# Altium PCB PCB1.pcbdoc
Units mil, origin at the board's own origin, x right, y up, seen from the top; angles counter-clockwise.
Board outline 3855 x 2840 mil, 4 copper layers (Top Layer, Inner1, Inner2, Bottom Layer); 26 components, 17 nets, 63 pads, 16 vias.
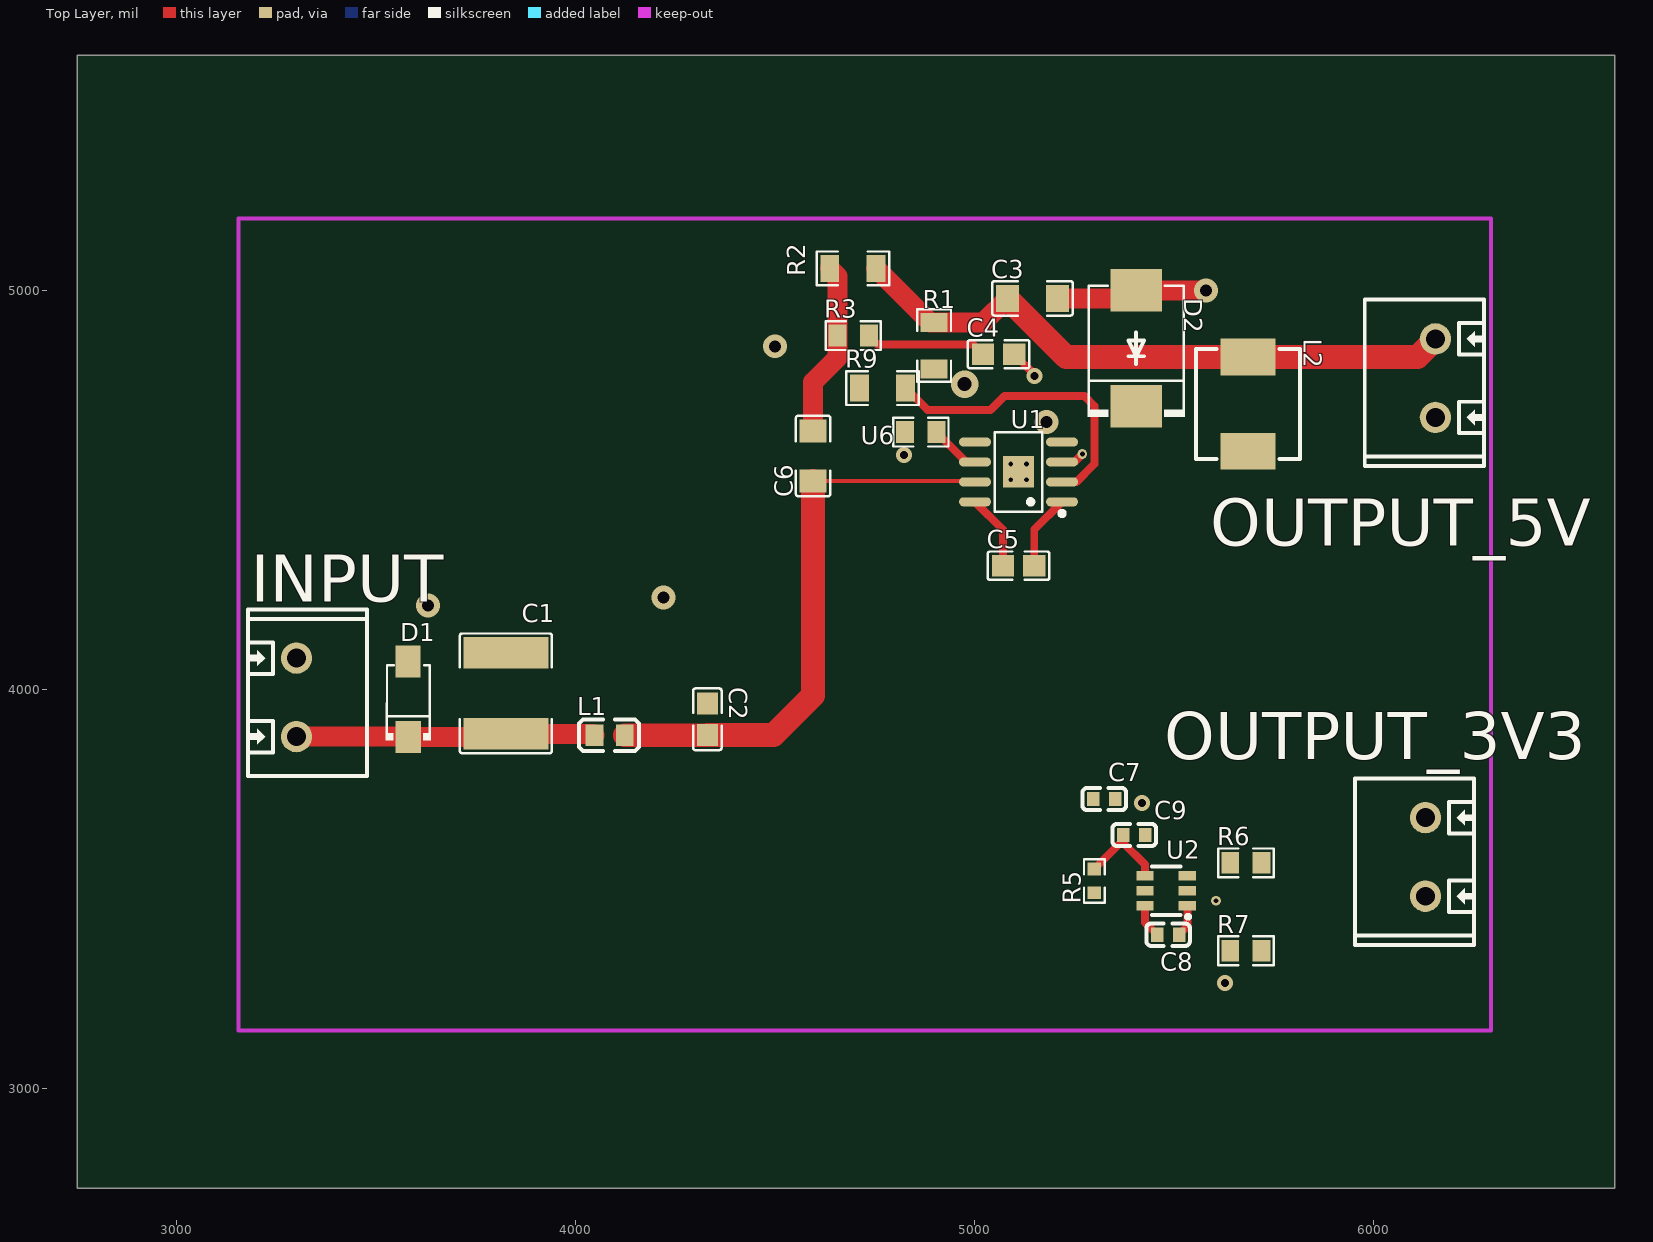
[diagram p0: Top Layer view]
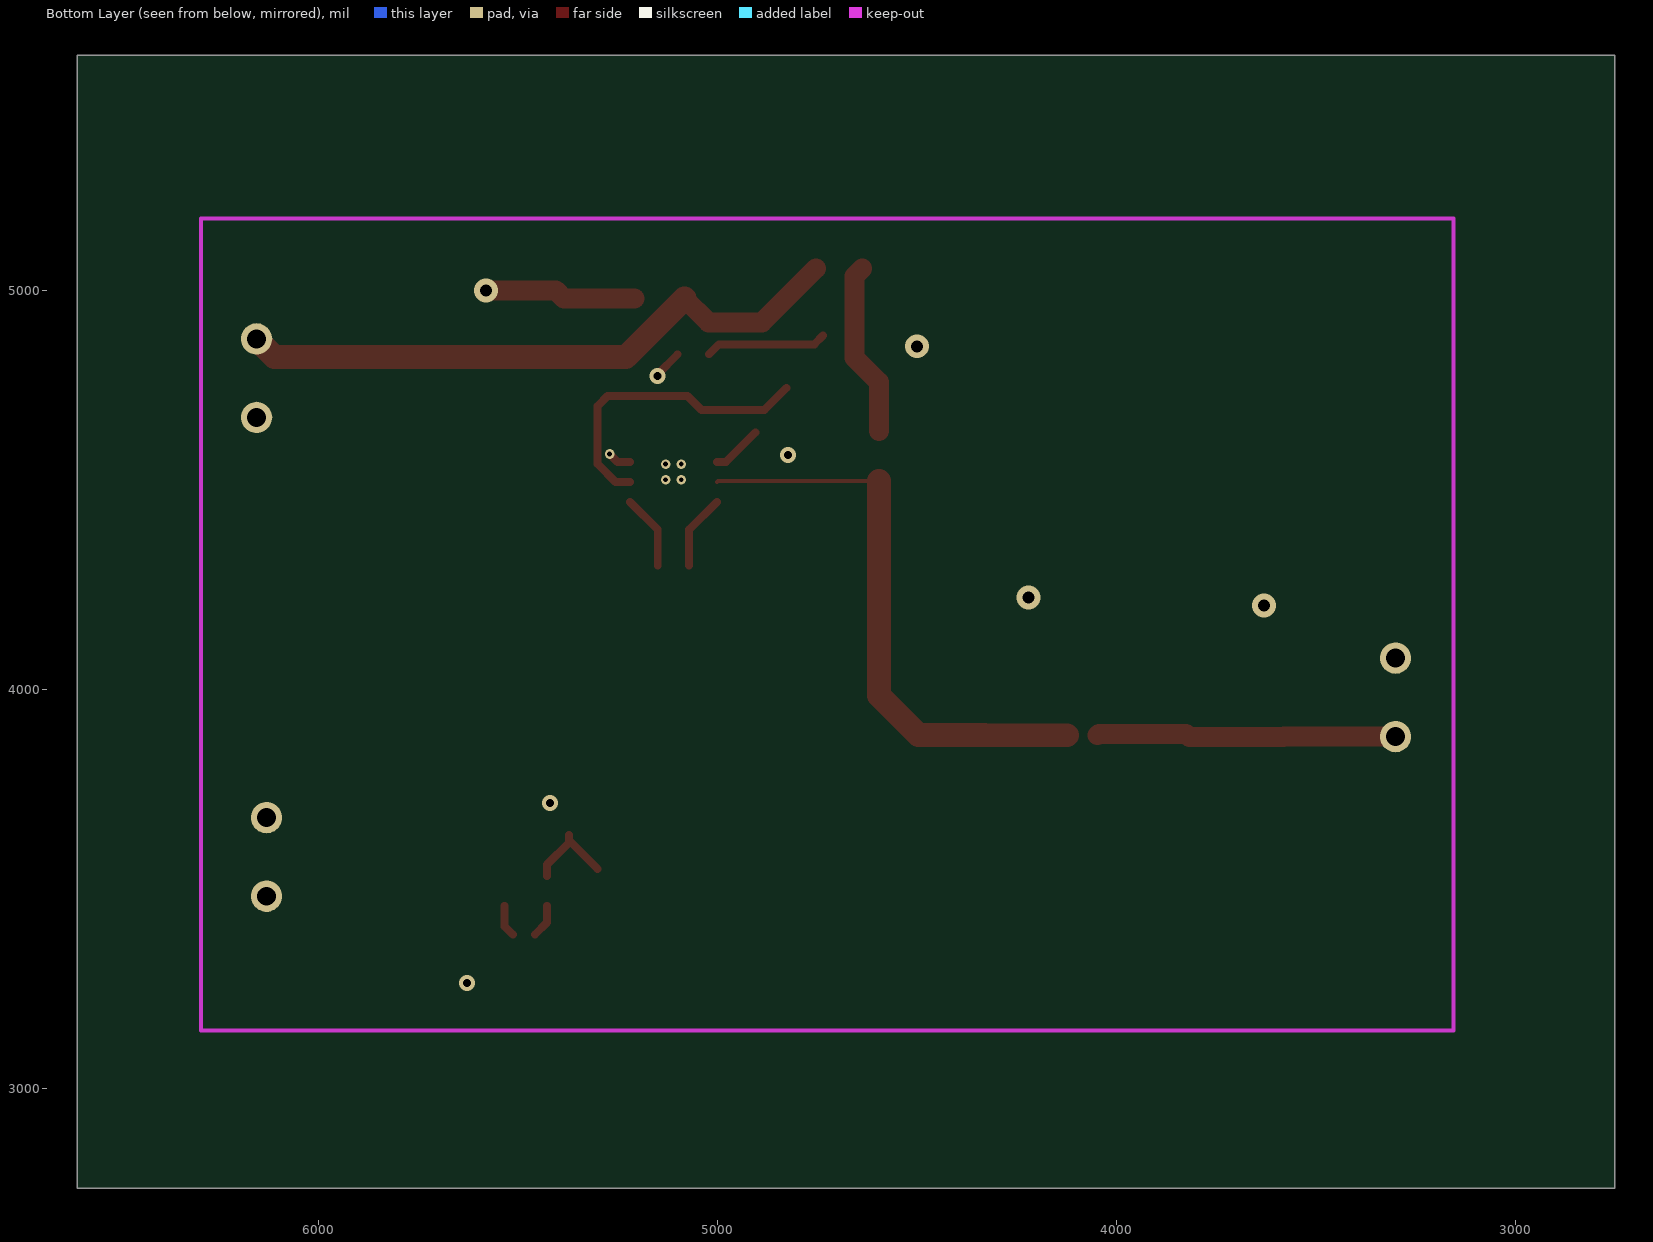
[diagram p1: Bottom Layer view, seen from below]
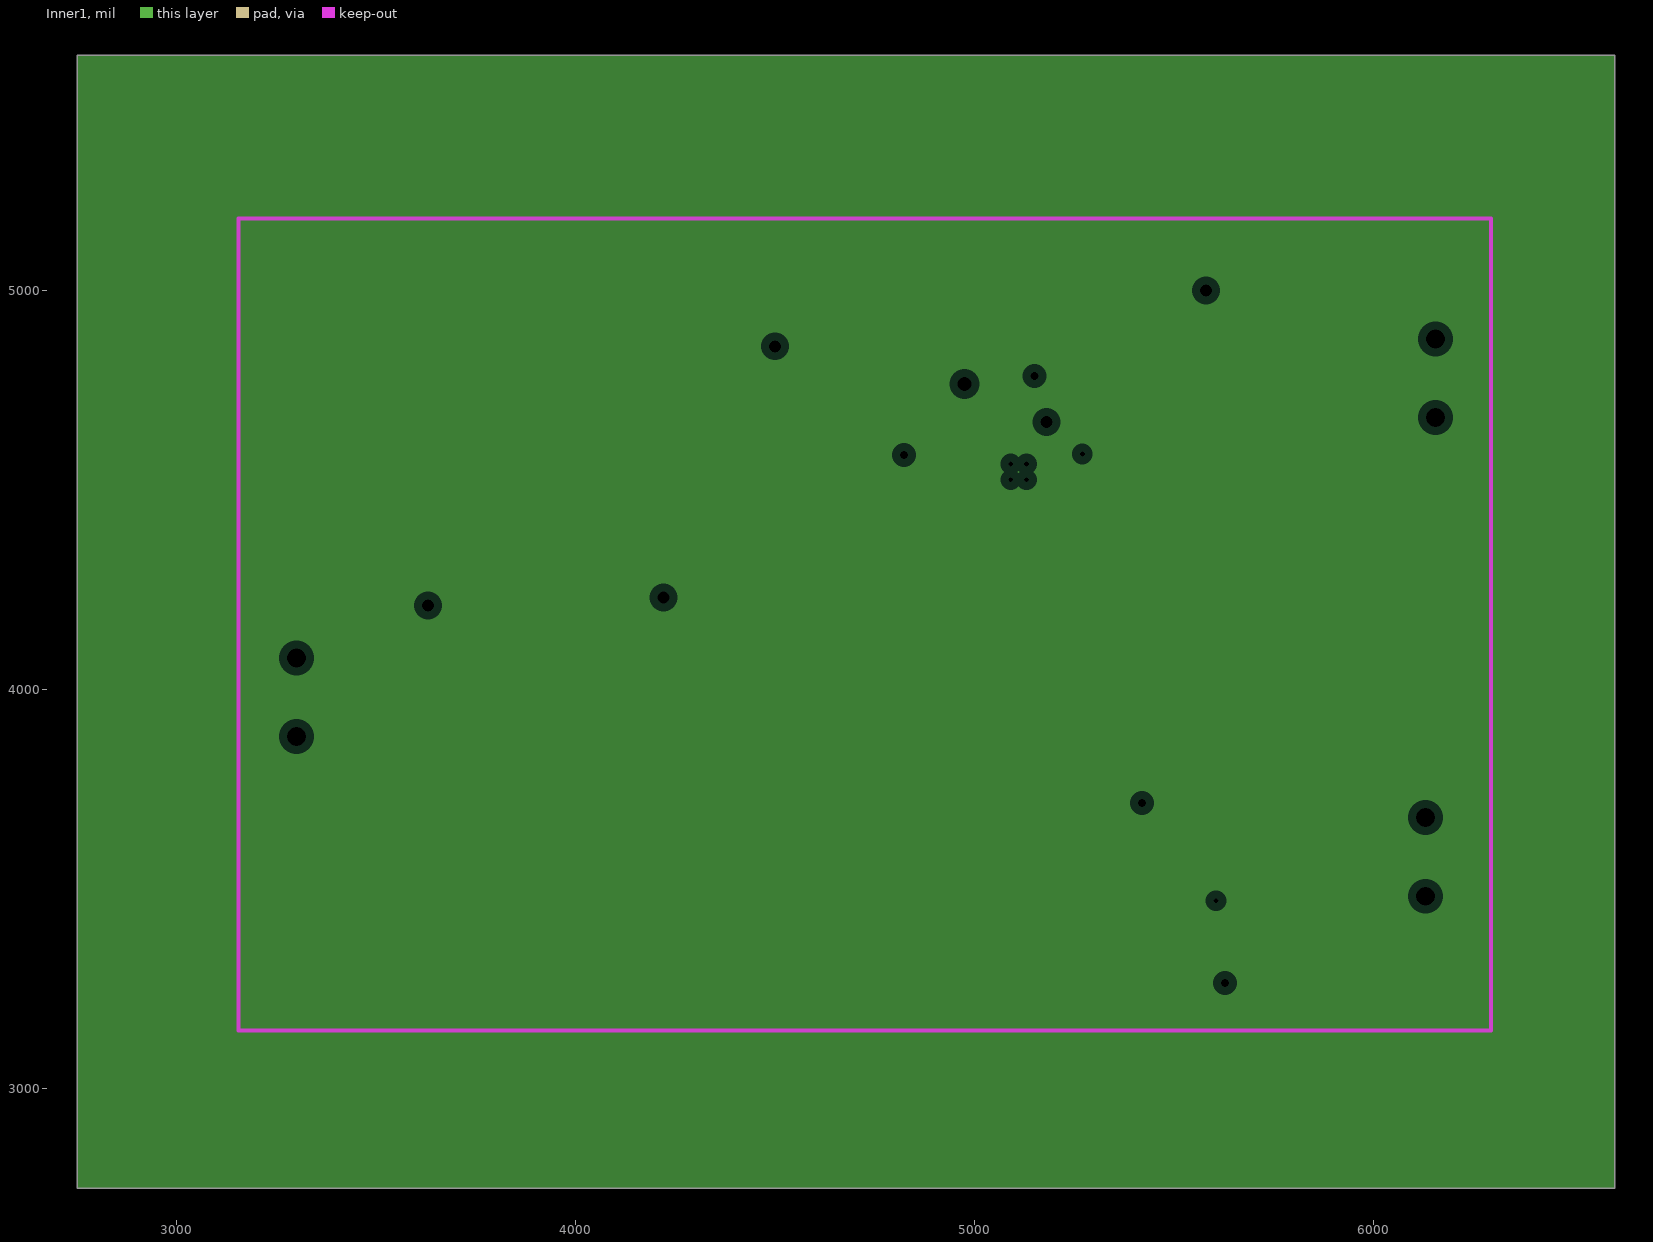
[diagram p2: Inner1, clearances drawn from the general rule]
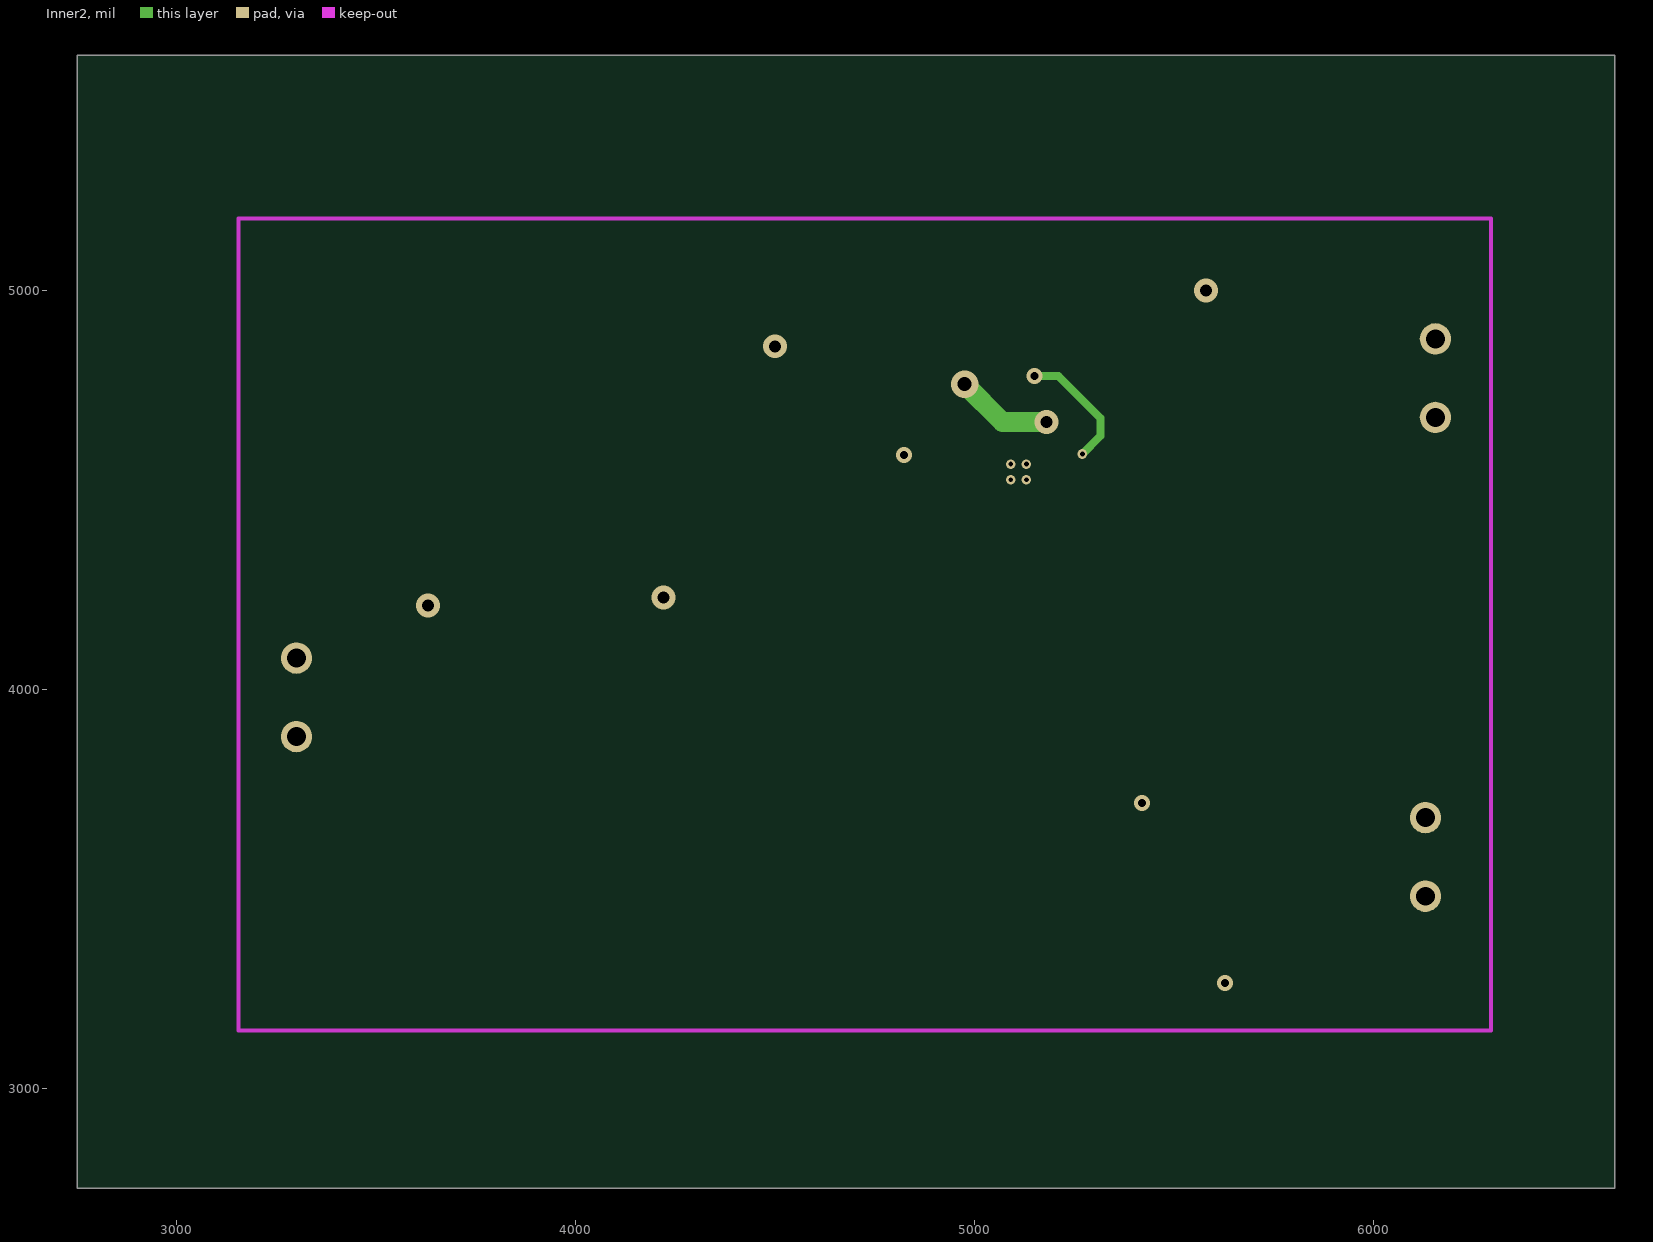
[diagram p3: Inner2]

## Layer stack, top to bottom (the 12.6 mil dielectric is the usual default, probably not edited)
Top Layer: signal copper (thickness not stored)
Dielectric: dielectric 12.6, FR-4, Dk 4.8
Inner1: plane copper (thickness not stored)
Dielectric: dielectric 12.6, FR-4, Dk 4.8
Inner2: signal copper (thickness not stored)
Dielectric: dielectric 12.6, FR-4, Dk 4.8
Bottom Layer: signal copper (thickness not stored)

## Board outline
6605,2750 2750,2750 2750,5590 6605,5590

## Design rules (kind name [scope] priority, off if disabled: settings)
BoardOutlineClearance copperThickness1oz [All] p0: genericclearance=10 ignorepadtopadclearanceinfootprint=FALSE except(0: Arc-SplitContinuation Track-SplitContinuation SMDPad-SplitContinuation THPad-SplitContinuation Via-SplitContinuation Fill-SplitContinuation Poly-SplitContinuation Region-SplitContinuation Text-SplitContinuation; 6: Track-CutoutEdge SMDPad-CutoutEdge THPad-CutoutEdge Via-CutoutEdge Region-CutoutEdge; 11.8: Track-OutlineEdge SMDPad-OutlineEdge THPad-OutlineEdge Via-OutlineEdge Fill-OutlineEdge Region-OutlineEdge Poly-OutlineEdge Text-OutlineEdge Fill-CutoutEdge)
BoardOutlineClearance copperThickness2oz [All] p0: genericclearance=10 ignorepadtopadclearanceinfootprint=FALSE except(0: Arc-SplitContinuation Track-SplitContinuation SMDPad-SplitContinuation THPad-SplitContinuation Via-SplitContinuation Fill-SplitContinuation Poly-SplitContinuation Region-SplitContinuation Text-SplitContinuation; 6: Track-CutoutEdge SMDPad-CutoutEdge THPad-CutoutEdge Via-CutoutEdge Region-CutoutEdge; 11.8: Track-OutlineEdge SMDPad-OutlineEdge THPad-OutlineEdge Via-OutlineEdge Fill-OutlineEdge Region-OutlineEdge Poly-OutlineEdge Text-OutlineEdge Fill-CutoutEdge)
Clearance copperThickness1oz [(InNet('$1N4446') OR InNet('AGND') OR InNet('VIN') OR InNet('GND') OR InNet('$1N1324') OR InNet('$1N1769') OR InNet('$1N1774') OR InNet('$1N1127') OR InNet('$1N1858') OR InNet('$1N3009') OR InNet('$1N3020') OR InNet('$1N3287') OR InNet('$1N1436') OR InNet('$1N3600') OR InNet('$1N3416') OR InNet('$1N4826') OR InNet('$1N1958'))] p1: gap=7 ignorepadtopadclearanceinfootprint=FALSE except(4: Track-Track; 6: Track-SMDPad SMDPad-SMDPad Track-THPad SMDPad-THPad THPad-THPad Track-Via SMDPad-Via THPad-Via Via-Via SMDPad-Fill THPad-Fill Via-Fill Fill-Fill Track-Region SMDPad-Region THPad-Region Via-Region Region-Region Track-Poly SMDPad-Poly THPad-Poly Via-Poly Fill-Poly Region-Poly Poly-Poly Track-Text SMDPad-Text THPad-Text Via-Text Fill-Text Region-Text Poly-Text Text-Text; 6.9: Track-Hole SMDPad-Hole THPad-Hole Via-Hole Fill-Hole Region-Hole Poly-Hole Text-Hole Sheet-Hole; 11.8: Track-Fill Fill-Region Track-Sheet SMDPad-Sheet THPad-Sheet Via-Sheet Fill-Sheet Region-Sheet Poly-Sheet Text-Sheet)
Clearance copperThickness2oz [All] p1: gap=7 ignorepadtopadclearanceinfootprint=FALSE except(6: Track-SMDPad SMDPad-SMDPad Track-THPad SMDPad-THPad THPad-THPad Track-Via SMDPad-Via THPad-Via Via-Via SMDPad-Fill THPad-Fill Via-Fill Fill-Fill Track-Region SMDPad-Region THPad-Region Via-Region Region-Region Track-Poly SMDPad-Poly THPad-Poly Via-Poly Fill-Poly Region-Poly Poly-Poly Track-Text SMDPad-Text THPad-Text Via-Text Fill-Text Region-Text Poly-Text Text-Text; 6.9: Track-Hole SMDPad-Hole THPad-Hole Via-Hole Fill-Hole Region-Hole Poly-Hole Text-Hole Sheet-Hole; 8: Track-Track; 11.8: Track-Fill Fill-Region Track-Sheet SMDPad-Sheet THPad-Sheet Via-Sheet Fill-Sheet Region-Sheet Poly-Sheet Text-Sheet)
DiffPairsRouting differentialPair [All] p1: maxuncoupledlength=10 minlimit=6 maxlimit=6 mostfreqgap=6 toplayer_minwidth=5 toplayer_prefwidth=10 toplayer_maxwidth=100 bottomlayer_minwidth=5 bottomlayer_prefwidth=10 bottomlayer_maxwidth=100 midlayer2_minwidth=5 midlayer2_prefwidth=10 midlayer2_maxwidth=100
PasteMaskExpansion pasteMaskExpansion [All] p1: expansion=0
PlaneConnect innerPlane [All] p1: planeconnectstyle=Relief reliefexpansion=20 reliefentries=4 reliefconductorwidth=10 reliefairgap=10
PolygonConnect copperRegion [All] p1: connectstyle=Relief reliefentries=4 reliefconductorwidth=30 polygonreliefangle="90 Angle" airgapwidth=10
PolygonConnect copperRegion1 [All] p1: connectstyle=Direct reliefentries=4 reliefconductorwidth=10 polygonreliefangle="90 Angle" airgapwidth=10
RoutingVias viaSize [All] p1: viastyle="Through Hole" holewidth=12 minholewidth=11.8 maxholewidth=248 width=24 minwidth=19.7 maxwidth=393.7
SolderMaskExpansion solderMaskExpansion [All] p1: useseparateexpansions=TRUE expansion=2 expansionbottom=2
Width copperThickness1oz [All] p1: maxlimit=100 minlimit=5 preferedwidth=10
Width copperThickness2oz [All] p1: maxlimit=100 minlimit=8 preferedwidth=50

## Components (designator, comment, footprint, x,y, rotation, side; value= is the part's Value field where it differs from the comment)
C1 "FS55X226K500EHG" C2220 3825,3990 r270 top
C2 "CL21B105KBFNNNE" C0805 4330,3925 r270 top
C3 "GCM31CR70J226KE23L" C1206 5145,4980 r0 top
C4 "CC0805JRNPO9BN151" C0805 5060,4840 r0 top
C5 "CAP_0805" C0805 5110,4310 r0 top
C6 "HGC1206R5106K500NSPJ" C1206 4595,4585 r90 top
C7 "CL10A226MP8NUNE" C0603 5325,3725 r180 top
C8 "CAP_0603" C0603 5485,3385 r0 top
C9 "CAP_0603" C0603 5400,3635 r180 top
D1 "SMAJ15A_C19077535" SMA_L4.3-W2.6-LS5.0-RD 3580,3975 r90 top
D2 "SS34_C154551" SMC_L6.9-W5.9-LS7.9-RD 5405,4855 r90 top
INPUT "DG301-5.0-02P-14-00A(H)" CONN-TH_DEGSON_DG301-5.0-02P 3300,3980 r270 top
L1 "BLM21PG221SN1D" L0805 4085,3885 r0 top
L2 "MWSA0603S-150MT" IND-SMD_L7.3-W6.8 5685,4715 r270 top
OUTPUT_3V3 "DG301-5.0-02P-14-00A(H)" CONN-TH_DEGSON_DG301-5.0-02P 6130,3580 r90 top
OUTPUT_5V "DG301-5.0-02P-14-00A(H)" CONN-TH_DEGSON_DG301-5.0-02P 6155,4780 r90 top
R1 "1206W4F2103T5E" R1206 4898.22,4861.78 r270 top
R2 "FRC1206F4022TS" R1206 4695,5055 r0 top
R3 "0805W8F1003T5E" R0805 4695.63,4886.89 r0 top
R5 "Res_0603" R0603 5300,3520 r90 top
R6 "Res_0805" R0805 5680,3565 r0 top
R7 "Res_0805" R0805 5680,3345 r0 top
R9 "Res_1206" R1206 4768.99,4755.16 r0 top
U1 "MP1584EN-LF-Z" SOIC-8_L5.0-W4.0-P1.27-LS6.0-BL-EP2.0 5110,4545 r90 top
U2 "TPS560430YFDBVR" SOT-23-6_L2.9-W1.6-P0.95-LS2.8-BR 5480,3495 r0 top
U6 "FRC0805F2492TS" R0805 4865,4645 r0 top

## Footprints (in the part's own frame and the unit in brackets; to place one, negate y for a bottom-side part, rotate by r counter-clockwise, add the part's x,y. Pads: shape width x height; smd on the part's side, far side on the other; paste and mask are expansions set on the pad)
C0603 [mm]
  rect 0.8x0.9 smd: 1(-0.7,0) 2(0.7,0)
  silkscreen extent -1.39,-0.71 1.39,0.71
C0805 [mm]
  rect 1.41x1.35 smd: 1(-1,0) 2(1,0)
  silkscreen extent -1.96,-0.9 1.96,0.9
C1206 [mm]
  rect 1.485x1.728 smd: 1(-1.593,0) 2(1.593,0)
  silkscreen extent -2.56,-1.09 2.56,1.09
C2220 [mm]
  rect 2.01x5.4 smd: 1(-2.58,0) 2(2.58,0)
  silkscreen extent -3.81,-2.93 3.81,2.93
CONN-TH_DEGSON_DG301-5.0-02P [mm]
  round 2 hole 1.2: 1(-2.5,0) 2(2.5,0)
  silkscreen extent -5.6,-3.1 5,4.5
IND-SMD_L7.3-W6.8 [mm]
  rect 2.35x3.5 smd: 1(-3,0) 2(3,0)
  silkscreen extent -3.5,-3.3 3.5,3.3
L0805 [mil]
  rect 44.59x54.21 smd: 1(-38.04,0) 2(38.04,0)
  silkscreen extent -77,-40 73,40
R0603 [mil]
  rect 31.75x34.02 smd: 1(-29.66,0) 2(29.66,0)
  silkscreen extent -55,-26 55,26
R0805 [mm]
  rect 1.133x1.377 smd: 1(-1,0) 2(1,0)
  silkscreen extent -1.76,-0.92 1.76,0.92
R1206 [mil]
  rect 47.54x66.97 smd: 1(-58.22,0) 2(58.22,0)
  silkscreen extent -91,-42 91,42
SMA_L4.3-W2.6-LS5.0-RD [mm]
  rect 2.046x1.62 smd: 1(-2.404,-0.009) 2(2.404,0.009)
  silkscreen extent -2.61,-1.44 2.16,1.44
SMC_L6.9-W5.9-LS7.9-RD [mm]
  rect 2.7x3.3 smd: 1(-3.686,0) 2(3.686,0)
  silkscreen extent -4.36,-3.1 3.98,3.1
SOIC-8_L5.0-W4.0-P1.27-LS6.0-BL-EP2.0 [mm]
  oval 0.574x2.038 smd: 1(-1.905,-2.769) 2(-0.635,-2.769) 3(0.635,-2.769) 4(1.905,-2.769) 5(1.905,2.769) 6(0.635,2.769) 7(-0.635,2.769) 8(-1.905,2.769)
  rect 2x2 smd: 9(0,0)
  silkscreen extent -2.79,-2.92 2.53,1.52
SOT-23-6_L2.9-W1.6-P0.95-LS2.8-BR [mm]
  rect 1.1x0.6 smd: 1(1.35,-0.95) 2(1.35,0) 3(1.35,0.95) 4(-1.35,0.95) 5(-1.35,0) 6(-1.35,-0.95)
  silkscreen extent -0.9,-1.78 1.52,1.55

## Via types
v1: diameter 24, hole 12, Top Layer to Bottom Layer, 5 vias
v2: diameter 60, hole 30, Top Layer to Bottom Layer, 4 vias
v3: diameter 40, hole 20, Top Layer to Bottom Layer, 4 vias
v4: diameter 69, hole 35, Top Layer to Inner2, 1 vias
v5: diameter 60, hole 30, Top Layer to Inner2, 1 vias
v6: diameter 24, hole 12, Top Layer to Inner1, 1 vias

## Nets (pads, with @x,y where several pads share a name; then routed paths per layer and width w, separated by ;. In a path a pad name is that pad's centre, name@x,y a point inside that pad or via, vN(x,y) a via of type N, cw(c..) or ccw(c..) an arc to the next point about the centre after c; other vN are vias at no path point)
$1N1127: C5.2 D2.1 L2.2 U1.1 | length 188.8
  Top Layer w20: C5.2 5149.37,4400.35 U1.1
$1N1324: C3.1 L2.1 OUTPUT_5V.2 R1.1 R2.2 | length 1552.2
  Top Layer w50: R2.2 R1.1@4888.22,4920 ; R1.1 5022.3,4920 C3.1
  Top Layer w59: C3.1 5229.19,4833.11 L2.1
  Top Layer w60: L2.1 6109.69,4833.11 OUTPUT_5V.2
$1N1436: R1.2 U1.4 | length 244.4
  Inner2 w50: v4(4975,4765) 5070,4670 v5(5180,4670)
$1N1769: C4.2 U1.3 | length 452.4
  Top Layer w20: C4.2 5150,4789.37 v3(5150,4785) ; U1.3 5250,4570 v1(5270,4590)
  Inner2 w20: v3(5150,4785) 5210,4785 5315,4680 5315,4635 v1(5270,4590)
$1N1774: C4.1 R3.2 | length 305.1
  Top Layer w20: R3.2 4756.89,4865 4995.63,4865 C4.1
$1N1858: C5.1 U1.8 | length 188.8
  Top Layer w20: U1.8 5070.63,4400.35 C5.1
$1N1958: U1.6 U6.2 | length 127.4
  Top Layer w20: U6.2@4904.37,4644.44 4978.81,4570 U1.6
$1N3009: C8.2 U2.1 | length 81.1
  Top Layer w20: C8.2 5533.15,3405.59 U2.1
$1N3020: C8.1 U2.6 | length 85.3
  Top Layer w20: U2.6 5426.85,3415.59 C8.1
$1N3287: C9.2 R5.2 U2.4 | length 227.6
  Top Layer w20: R5.2 C9.2@5372.44,3622.1 ; C9.2 C9.2@5372.44,3622.1 ; U2.4 5426.85,3560.68 5372.44,3615.09 C9.2@5372.44,3622.1
$1N3416: R6.1 U2.3
$1N3600: OUTPUT_3V3.2 R6.2 R7.2
$1N4446: C1.2 D1.1 INPUT.2 L1.1 | length 752.2
  Top Layer w50: INPUT.2 3579.15,3881.57 D1.1 3816.93,3880.36 C1.2 4043.54,3888.42 L1.1
$1N4826: R9.2 U1.2 | length 765.1
  Top Layer w20: R9.2 4882.37,4700 5040,4700 5075,4735 5275,4735 5300,4710 5300,4565 5255,4520 U1.2
AGND: C1.1 C2.1 C3.2 C6.2 C7.1 C9.1 D1.2 D2.2 INPUT.1 OUTPUT_3V3.1 OUTPUT_5V.1 R2.1 R3.1 R7.1 U6.1 | length 821.4
  Top Layer w50: C6.2 4595,4770 4656.26,4831.26 R3.1 4656.26,5035.52 R2.1 ; C3.2 5384.87,4980 D2.2 5579.87,5000.13 v2(5580,5000)
  other v2: 3630,4210 4220,4230 4500,4860
  other v3: 5627.78,3263.64 5420,3715 4822.77,4587.31
GND: U1.5 U1.9 U2.2
  other v1: 5090.31,4525.31 5129.69,4525.31 5090.31,4564.69 5129.69,4564.69
  other v6: 5605,3470
VIN: C2.2 C6.1 C7.2 L1.2 R5.1 R9.1 U1.7 U2.5 | length 1457.6
  Top Layer w10: C6.1 4998.68,4522.3 U1.7
  Top Layer w60: L1.2 4329.37,3885 C2.2 4495.63,3885.63 4595,3985 C6.1

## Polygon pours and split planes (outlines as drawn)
GND on Top Layer (solid, remove dead copper, pour order 36): 3065,5270 6350,5270 6350,3000 3065,3000
AGND on Bottom Layer (solid, remove dead copper, pour order 38): 3000,5340 6355,5340 6355,3100 3000,3100
VIN on Top Layer (solid, remove dead copper, pour order 0): 4595,4522.3 4625,4552.3 4927.7,4552.3 4935,4545 5004.08,4545 5029.08,4520 5005,4495.92 5005,4490 4630,4490 4625,4495 4622.3,4495
$1N1127 on Top Layer (solid, remove dead copper, pour order 2): 5192.08,4470 5217.08,4495 5260,4495 5325,4560 5325,4735 5498.76,4735 5498.76,4473.42 5405,4379.65 5310.35,4379.65 5230,4460 5202.08,4460
VIN on Top Layer (solid, remove dead copper, pour order 4): 4666.69,4755.16 4666.69,4581.69 4641.29,4515 4785.32,4515 4785.32,4564.68 4760,4590 4760,4750 4754.84,4755.16
AGND on Top Layer (solid, remove dead copper, pour order 6): 4795,4675 4855,4675 4855,4562.23 4792.84,4562.23 4792.84,4672.84
$1N1127 on Top Layer (solid, remove dead copper, pour order 8): 5480,4665 5805,4665 5805,4426.15 5445,4426.15 5445,4630
$1N1436 on Top Layer (solid, remove dead copper, pour order 10): 4898.22,4835.09 4959.91,4835.09 5015,4780 5015,4750 4990,4725 4940,4725 4890,4775 4890,4826.87
$1N1436 on Top Layer (solid, remove dead copper, pour order 12): 5145,4705 5265,4705 5265,4605 5145,4605
VIN on Top Layer (solid, remove dead copper, pour order 14): 5145,3725 5145,3425.5 5249.5,3425.5 5250,3425 5360.96,3425 5360.96,3509.04 5350,3520 5257.61,3520 5257.61,3587.61 5325,3655 5325,3725
VIN on Top Layer (solid, remove dead copper, pour order 16): 5360,3522.74 5465,3515 5465,3474.76 5360,3455.67
$1N3416 on Top Layer (solid, remove dead copper, pour order 18): 5505,3515 5680,3515 5680,3619.47 5510.53,3619.47 5505,3625
$1N3600 on Top Layer (solid, remove dead copper, pour order 20): 5687.43,3601.11 5687.43,3276.95 5778.05,3276.95 5780,3275 5780,3614.09 5687.43,3614.09
$1N3600 on Top Layer (solid, remove dead copper, pour order 22): 5745,3640 5965,3640 6044.25,3755 6242.85,3755 6242.85,3552.59 6007.59,3552.59 5930,3475 5780.54,3475 5745,3510.54
AGND on Top Layer (solid, remove dead copper, pour order 24): 5350,3780 5350,3670.85 5400,3670.85 5400,3633.82 5426.78,3607.04 5469.69,3607.04 5469.69,3775.31 5465,3780
AGND on Top Layer (solid, remove dead copper, pour order 26): 5640,3405 5585,3405 5585,3235 5590,3230 5658.63,3230 5658.63,3405.85 5640.85,3405.85
GND on Top Layer (solid, remove dead copper, pour order 28): 5500,3510 5635,3510 5635,3441.94 5598.06,3441.94 5565,3475 5505,3475 5500,3480
AGND on Top Layer (solid, remove dead copper, pour order 30): 3220,3975 4180.38,3975 4230.38,3925 4396.7,3925 4396.7,4305 3231.97,4305 3219.67,4292.7 3219.67,3975.33
AGND on Top Layer (solid, remove dead copper, pour order 32): 4630,5125 4630,4986.06 4656.26,4959.8 4656.26,4781.26 4630,4755 4630,4585 4384.23,4585 4384.23,5124.23 4385,5125
VIN on Top Layer (solid, remove dead copper, pour order 34): 4455,3995 5315,3995 5320,3990 5320,3635 4455,3635

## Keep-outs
Board Outline Layer:
  lines w10: 3155,3145.39 6294.61,3145.39 6294.61,5180 3155,5180 3155,3145.39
